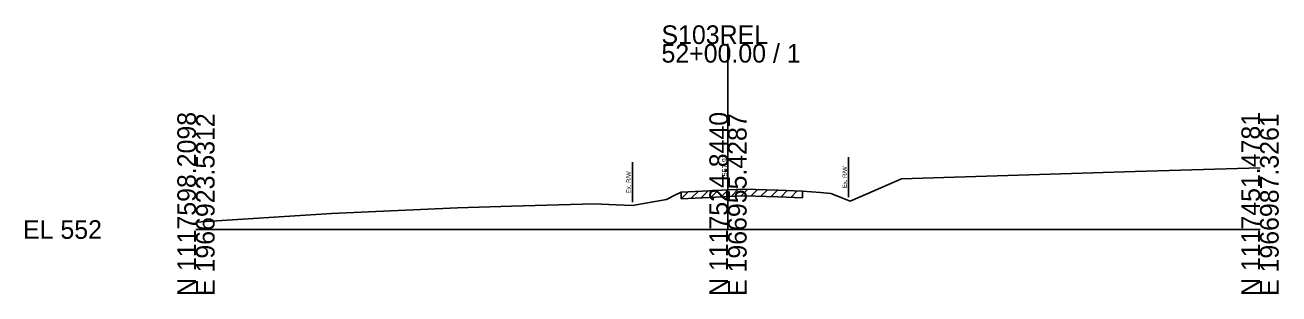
# Model space of a CAD drawing. Extents: x -26 to 163, y -10 to 24518.
# Drawn here: x -25.7 to 162.8, y 2490.3 to 2530.8 of the extents above; entities that cross this region are included whole.
import ezdxf

# ---------------------------------------------------------------- set-up
doc = ezdxf.new("R2010")
doc.units = 0
for name, color, linetype in [('RD_GPK_XS_Cell', 7, 'Continuous'), ('RD_XS_ExGround', 7, 'Continuous'), ('RD_XS_ExPaveRet', 7, 'Continuous'), ('RD_XS_ExRW', 7, 'Continuous'), ('RD_XS_TX_Elev_EX', 7, 'Continuous')]:
    doc.layers.add(name, color=color, linetype=linetype)

msp = doc.modelspace()

# ---------------------------------------------------------------- linework, layer by layer
at = {"layer": 'RD_GPK_XS_Cell'}
for p, q in [((80, 2500), (80, 2527.91)), ((0, 2500), (80, 2500)), ((80, 2500), (160, 2500))]:
    msp.add_line(p, q, dxfattribs=at)
at = {"layer": 'RD_XS_ExGround'}
msp.add_lwpolyline([(0, 2501.1), (20.39, 2502.4), (39.33, 2503.26), (47.45, 2503.5), (59.89, 2503.86), (63.18, 2503.71), (65.63, 2503.62), (67.91, 2504.02), (70.75, 2504.51), (72, 2505.18), (72.96, 2505.61), (77.15, 2505.83), (80, 2505.97), (82.41, 2506.09), (87.48, 2505.9), (91.2, 2505.77), (93.93, 2505.55), (95.48, 2505.43), (96.62, 2504.99), (98.39, 2504.27), (101.02, 2505.42), (106.11, 2507.61), (141.2, 2508.72), (160, 2509.3)], dxfattribs=at)
at = {"layer": 'RD_XS_ExPaveRet'}
for p, q in [((72.96, 2504.61), (74.01, 2505.66)), ((72.96, 2504.61), (72.96, 2505.61)), ((74.46, 2504.69), (75.51, 2505.74)), ((75.96, 2504.77), (77.01, 2505.82)), ((77.46, 2504.85), (78.51, 2505.9)), ((78.96, 2504.92), (80.01, 2505.97)), ((80.46, 2504.99), (81.51, 2506.05)), ((81.96, 2505.07), (82.96, 2506.07)), ((83.46, 2505.05), (84.42, 2506.02)), ((84.96, 2505), (85.92, 2505.96)), ((86.46, 2504.94), (87.42, 2505.91)), ((87.96, 2504.89), (88.92, 2505.85)), ((89.46, 2504.83), (90.42, 2505.8)), ((91.2, 2505.77), (91.2, 2504.77)), ((72.96, 2504.61), (77.15, 2504.83)), ((77.15, 2504.83), (80, 2504.97)), ((80, 2504.97), (82.41, 2505.09)), ((82.41, 2505.09), (87.48, 2504.9)), ((87.48, 2504.9), (91.2, 2504.77))]:
    msp.add_line(p, q, dxfattribs=at)
at = {"layer": 'RD_XS_ExRW'}
for p, q in [((65.63, 2510.12), (65.63, 2504.12)), ((98.12, 2510.88), (98.12, 2504.88))]:
    msp.add_line(p, q, dxfattribs=at)

# ---------------------------------------------------------------- texts
at = {"layer": 'RD_GPK_XS_Cell'}
for s, p in [('S103REL', (70, 2527.91)), ('52+00.00 / 1', (70, 2525.11)), ('EL 552', (-26, 2498.6))]:
    msp.add_text(s, height=2.8, dxfattribs=at).set_placement(p)
for s, p in [('N 1117598.2098', (0, 2490)), ('E 1966923.5312', (2.8, 2490)), ('N 1117524.8440', (80, 2490)), ('E 1966955.4287', (82.8, 2490)), ('N 1117451.4781', (160, 2490)), ('E 1966987.3261', (162.8, 2490))]:
    msp.add_text(s, height=2.8, rotation=90, dxfattribs=at).set_placement(p)
at = {"layer": 'RD_XS_ExRW'}
for p in [(97.87, 2506.22), (65.38, 2505.46)]:
    msp.add_text('Ex. R/W ', height=0.65, rotation=90, dxfattribs=at).set_placement(p)
at = {"layer": 'RD_XS_TX_Elev_EX'}
msp.add_text('557.97', height=0.8, rotation=90, dxfattribs=at).set_placement((79.9, 2507.97))

doc.saveas('drawing.dxf')
